// Mitsubishi GX Works2 project: 练习-画三角形(王)   PLC: FX3U/FX3UC

PROGRAM MAIN
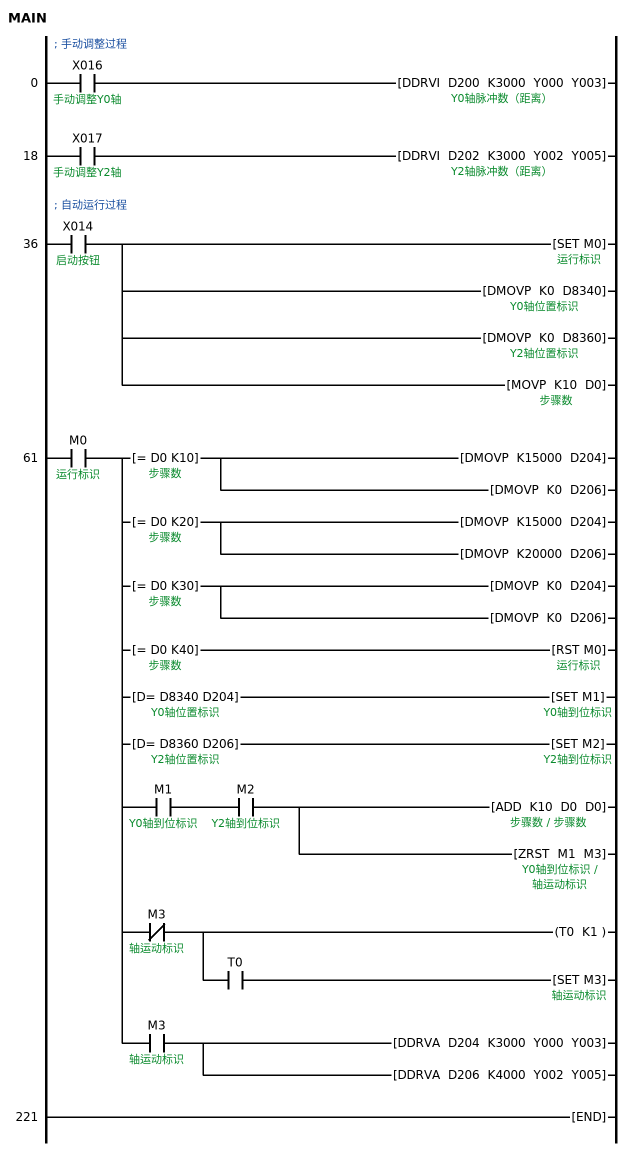
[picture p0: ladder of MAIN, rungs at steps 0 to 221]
; 手动调整过程
0     LD      X016  ; 手动调整Y0轴
      DDRVI   D200 K3000 Y000 Y003  ; Y0轴脉冲数（距离）
18    LD      X017  ; 手动调整Y2轴
      DDRVI   D202 K3000 Y002 Y005  ; Y2轴脉冲数（距离）
; 自动运行过程
36    LD      X014  ; 启动按钮
      SET     M0  ; 运行标识
      DMOVP   K0 D8340  ; Y0轴位置标识
      DMOVP   K0 D8360  ; Y2轴位置标识
      MOVP    K10 D0  ; 步骤数
61    LD      M0  ; 运行标识
      MPS
      AND=    D0 K10  ; 步骤数
      DMOVP   K15000 D204
        [note] 1.A到B运行
      DMOVP   K0 D206
      MRD
      AND=    D0 K20  ; 步骤数
      DMOVP   K15000 D204
        [note] 2.B到C运行
      DMOVP   K20000 D206
      MRD
      AND=    D0 K30  ; 步骤数
      DMOVP   K0 D204
        [note] 3.C到A运行
      DMOVP   K0 D206
      MRD
      AND=    D0 K40  ; 步骤数
      RST     M0  ; 运行标识
        [note] 三角形完成后复位M0
      MRD
      ANDD=   D8340 D204  ; Y0轴位置标识
      SET     M1  ; Y0轴到位标识
      MRD
      ANDD=   D8360 D206  ; Y2轴位置标识
      SET     M2  ; Y2轴到位标识
      MRD
      AND     M1  ; Y0轴到位标识
      AND     M2  ; Y2轴到位标识
      ADD     K10 D0 D0
        [note] 步骤数自加10
      ZRST    M1 M3  ; 轴运动标识
        [note] Y0、Y2轴到位后复位M1-3
      MRD
      ANI     M3  ; 轴运动标识
      OUT     T0 K1
        [note] 硬件响应速度跟不上，手动断开
      AND     T0
      SET     M3  ; 轴运动标识
        [note] 各步之间间隔100ms
      MPP
      AND     M3  ; 轴运动标识
      DDRVA   D204 K3000 Y000 Y003
        [note] 数据输出过程
      DDRVA   D206 K4000 Y002 Y005
221   END
END_PROGRAM
